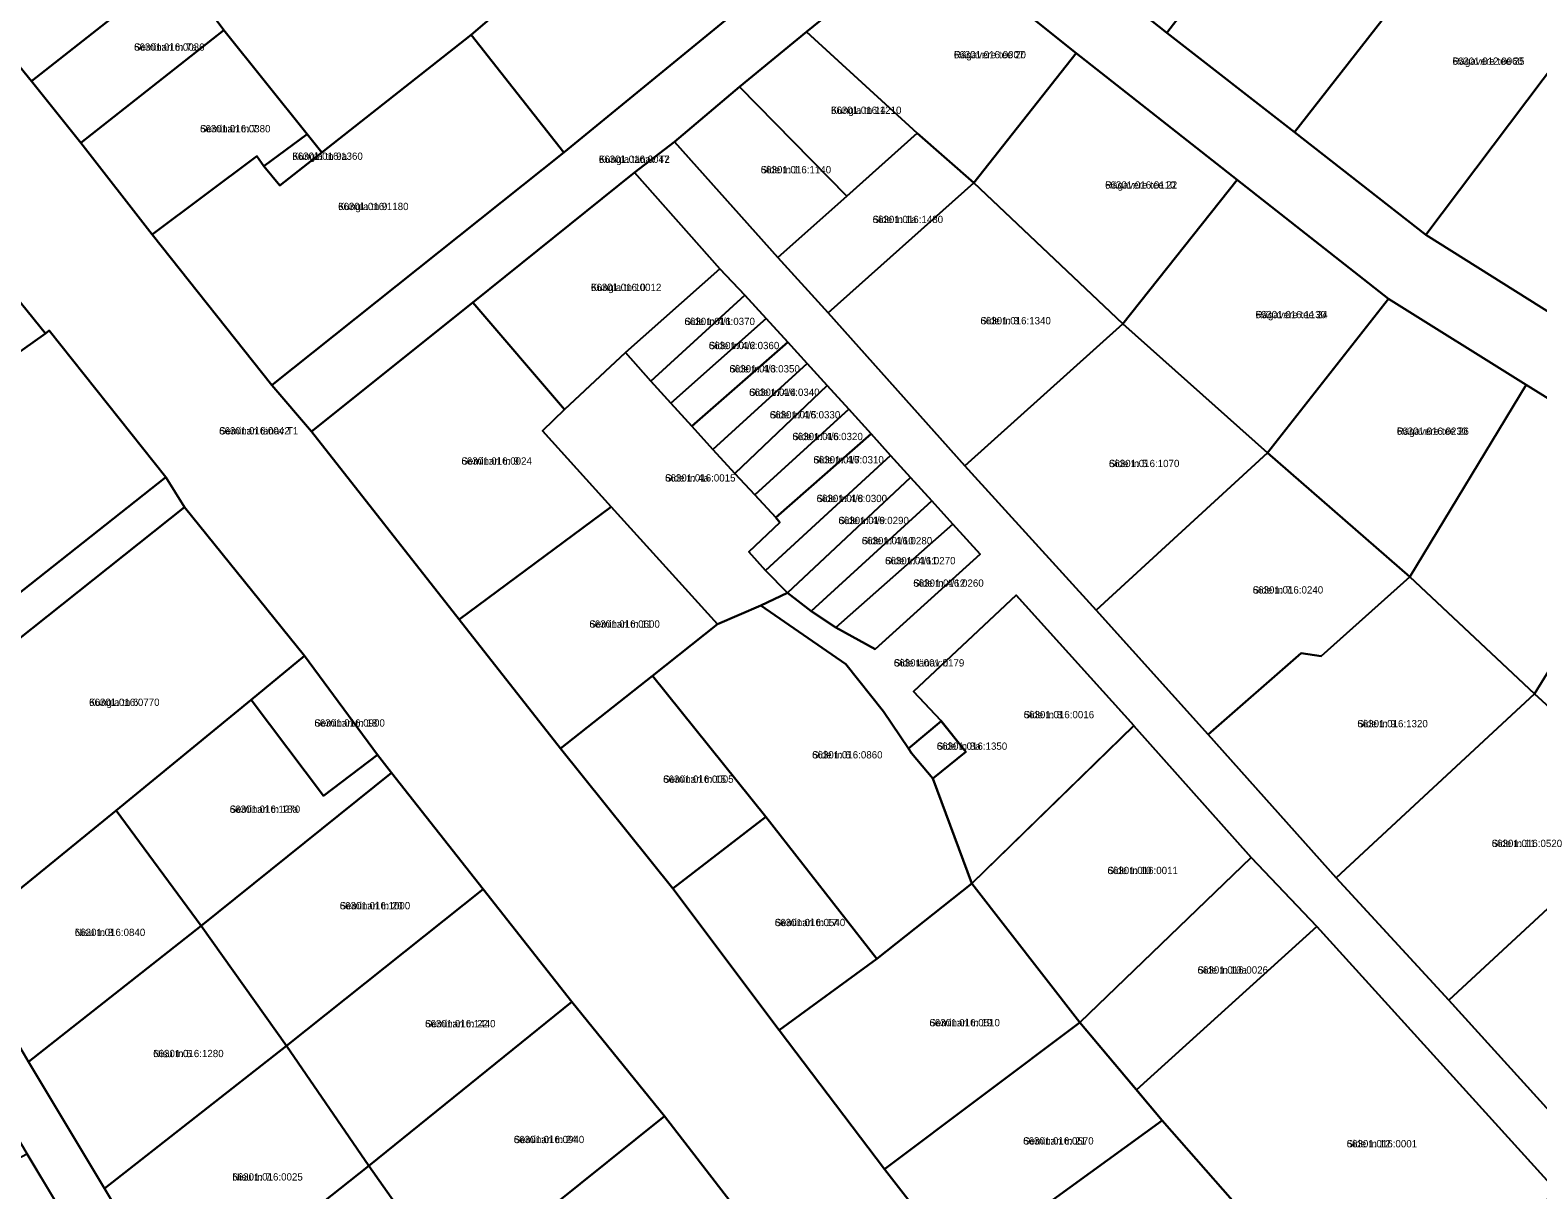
# Model space of a CAD drawing. Extents: x 632278 to 636344, y 6578401 to 6583362.
# Drawn here: x 634783.1 to 635093.3, y 6580529.5 to 6580768.1 of the extents above; entities that cross this region are included whole.
import ezdxf

# ---------------------------------------------------------------- set-up
doc = ezdxf.new("R2010")
doc.units = 0
for name, color, linetype in [('L_AADRESS', 7, 'Continuous'), ('PIIR', 7, 'Continuous'), ('TUNNUS', 7, 'Continuous')]:
    doc.layers.add(name, color=color, linetype=linetype)

msp = doc.modelspace()

# ---------------------------------------------------------------- linework, layer by layer
at = {"layer": 'PIIR'}
for points in [[(634823.24, 6580869.23), (634828.29, 6580865.31), (634831.8, 6580869.51), (634847.15, 6580857.94), (634862.57, 6580846.46), (634870.06, 6580838.92), (634888.87, 6580818.57), (634892.77, 6580814.98), (634907.16, 6580795.65), (634873.8, 6580767.13), (634843.07, 6580742.91), (634840.06, 6580746.68), (634822.92, 6580768.08), (634819.98, 6580772.06), (634822.28, 6580774.15), (634815.33, 6580782.85), (634813.98, 6580781.78), (634811.16, 6580779.56), (634801.59, 6580792.39), (634802.72, 6580793.42), (634817.17, 6580805.59), (634823.5, 6580810.97), (634823.96, 6580814.19), (634803.09, 6580842.19)], [(634873.8, 6580767.13), (634907.16, 6580795.65), (634915.86, 6580804.18), (634929.16, 6580820.76), (634957.76, 6580796.1), (634892.88, 6580742.94)], [(634995.71, 6580821.21), (635034.95, 6580790.95), (635016.95, 6580767.52), (634978.25, 6580798.29)], [(635055.26, 6580817.21), (635075.83, 6580801.21), (635082.16, 6580796.88), (635043.23, 6580747.12), (635016.95, 6580767.52), (635034.95, 6580790.95)], [(634802.72, 6580793.42), (634801.59, 6580792.39), (634811.16, 6580779.56), (634783.36, 6580757.62), (634769.78, 6580774.21), (634799.14, 6580797.48)], [(634832.82, 6580695.01), (634892.88, 6580742.94), (634957.76, 6580796.1), (634967.68, 6580787.95), (634942.84, 6580767.78), (634929.01, 6580756.42), (634915.67, 6580745.14), (634907.44, 6580738.83), (634874.12, 6580712.08), (634840.98, 6580685.48)], [(635043.23, 6580747.12), (635082.16, 6580796.88), (635095.73, 6580785.69), (635108.29, 6580776.43), (635070.3, 6580725.98)], [(634942.84, 6580767.78), (634967.68, 6580787.95), (634998.34, 6580763.36), (634977.26, 6580736.66), (634965.61, 6580746.87)], [(634815.33, 6580782.85), (634822.28, 6580774.15), (634819.98, 6580772.06), (634822.92, 6580768.08), (634793.5, 6580744.88), (634783.36, 6580757.62), (634811.15, 6580779.53), (634813.98, 6580781.78)], [(635070.3, 6580725.98), (635108.29, 6580776.43), (635115.42, 6580770.48), (635135.9, 6580754.85), (635099.43, 6580707.69)], [(634831.13, 6580740.14), (634829.72, 6580742.18), (634808.13, 6580726.06), (634793.5, 6580744.88), (634822.92, 6580768.08), (634840.06, 6580746.68)], [(634808.13, 6580726.06), (634829.72, 6580742.18), (634831.13, 6580740.14), (634834.47, 6580736.14), (634843.07, 6580742.91), (634873.8, 6580767.13), (634892.88, 6580742.94), (634832.82, 6580695.01)], [(634942.84, 6580767.78), (634965.61, 6580746.87), (634951.12, 6580733.96), (634929.01, 6580756.42)], [(635031.47, 6580737.28), (635007.9, 6580707.63), (634977.26, 6580736.66), (634998.34, 6580763.36)], [(634936.92, 6580721.34), (634915.67, 6580745.14), (634929.01, 6580756.42), (634951.12, 6580733.96)], [(634831.13, 6580740.14), (634840.06, 6580746.68), (634843.07, 6580742.91), (634834.47, 6580736.14)], [(634936.92, 6580721.34), (634951.12, 6580733.96), (634965.61, 6580746.87), (634977.26, 6580736.66), (634947.28, 6580709.92)], [(634907.44, 6580738.83), (634925, 6580718.99), (634905.59, 6580701.73), (634893, 6580690.02), (634874.12, 6580712.08)], [(634947.28, 6580709.92), (634977.26, 6580736.66), (635007.9, 6580707.63), (634975.39, 6580678.46)], [(635031.47, 6580737.28), (635062.56, 6580712.81), (635037.69, 6580681.14), (635007.9, 6580707.63)], [(634754.64, 6580720.33), (634767.52, 6580728.66), (634786.21, 6580705.69), (634769.31, 6580693.77), (634750.53, 6580717.31)], [(634905.59, 6580701.73), (634925, 6580718.99), (634930.14, 6580713.55), (634910.79, 6580695.84)], [(634874.12, 6580712.08), (634893, 6580690.02), (634888.51, 6580685.67), (634902.65, 6580669.99), (634871.35, 6580646.8), (634840.98, 6580685.48)], [(634910.79, 6580695.84), (634930.14, 6580713.55), (634934.55, 6580708.75), (634914.89, 6580691.34)], [(635090.91, 6580695.09), (635066.99, 6580655.6), (635037.69, 6580681.14), (635062.56, 6580712.81)], [(634914.89, 6580691.34), (634934.55, 6580708.75), (634939, 6580703.9), (634919.22, 6580686.57)], [(634975.39, 6580678.46), (635007.9, 6580707.63), (635037.69, 6580681.14), (635002.44, 6580648.74)], [(634723.93, 6580659.68), (634730.28, 6580664.53), (634721.26, 6580676.15), (634722.32, 6580678.87), (634732.5, 6580687.67), (634740.73, 6580676.25), (634749.82, 6580683.43), (634750.6, 6580682.22), (634752.63, 6580681.59), (634769.31, 6580693.77), (634786.21, 6580705.69), (634786.98, 6580706.28), (634810.95, 6580676.09), (634749.17, 6580627.28)], [(634905.59, 6580701.73), (634910.79, 6580695.84), (634914.89, 6580691.34), (634919.22, 6580686.57), (634923.56, 6580681.78), (634928.1, 6580676.87), (634932.18, 6580672.48), (634936.51, 6580667.78), (634937.35, 6580666.77), (634930.97, 6580660.76), (634934.41, 6580656.91), (634938.91, 6580652.32), (634933.4, 6580649.71), (634924.52, 6580645.84), (634902.65, 6580669.99), (634888.51, 6580685.67), (634893, 6580690.02)], [(634923.56, 6580681.78), (634919.22, 6580686.57), (634939, 6580703.9), (634942.97, 6580699.52)], [(634923.56, 6580681.78), (634942.97, 6580699.52), (634947.05, 6580694.97), (634928.1, 6580676.87)], [(634932.18, 6580672.48), (634928.1, 6580676.87), (634947.05, 6580694.97), (634951.54, 6580690.09)], [(635066.99, 6580655.6), (635090.91, 6580695.09), (635120.58, 6580676.71), (635092.61, 6580631.5)], [(634932.18, 6580672.48), (634951.54, 6580690.09), (634956.11, 6580685.04), (634936.51, 6580667.78)], [(634930.97, 6580660.76), (634937.35, 6580666.77), (634936.51, 6580667.78), (634956.11, 6580685.04), (634960.09, 6580680.58), (634934.41, 6580656.91)], [(634934.41, 6580656.91), (634960.09, 6580680.58), (634964.24, 6580676.02), (634938.91, 6580652.32)], [(635002.44, 6580648.74), (635037.69, 6580681.14), (635066.99, 6580655.6), (635048.71, 6580639.29), (635044.62, 6580639.92), (635025.47, 6580623.18)], [(635118.04, 6580608.34), (635092.61, 6580631.5), (635120.58, 6580676.71), (635149.13, 6580659)], [(634627.56, 6580552.33), (634672.16, 6580573.77), (634697.15, 6580585.77), (634749.17, 6580627.28), (634810.95, 6580676.09), (634814.85, 6580669.93), (634751.98, 6580619.99), (634754.12, 6580617.28), (634691.25, 6580567.83), (634680.94, 6580563.02), (634659.14, 6580553.09), (634633.69, 6580540.22)], [(634938.91, 6580652.32), (634964.24, 6580676.02), (634968.59, 6580671.22), (634943.8, 6580648.55)], [(634943.8, 6580648.55), (634968.59, 6580671.22), (634972.96, 6580666.42), (634948.89, 6580645.15)], [(634754.12, 6580617.28), (634751.98, 6580619.99), (634814.85, 6580669.93), (634839.5, 6580639.31), (634828.53, 6580630.32), (634800.72, 6580607.55), (634777.05, 6580588.16)], [(634911.12, 6580635.26), (634892.17, 6580620.29), (634871.35, 6580646.8), (634902.65, 6580669.99), (634924.52, 6580645.84)], [(634978.57, 6580660.25), (634956.93, 6580640.7), (634948.89, 6580645.15), (634972.96, 6580666.42)], [(635025.47, 6580623.18), (635044.62, 6580639.92), (635048.71, 6580639.29), (635066.99, 6580655.6), (635092.61, 6580631.5), (635051.82, 6580593.68)], [(634985.94, 6580651.81), (635010.2, 6580625.04), (634976.83, 6580592.52), (634968.81, 6580614.09), (634975.63, 6580619.58), (634970.46, 6580626.03), (634964.82, 6580632.01)], [(634911.12, 6580635.26), (634924.52, 6580645.84), (634933.4, 6580649.71), (634950.9, 6580637.66), (634958.68, 6580627.87), (634963.8, 6580620.27), (634964.45, 6580619.32), (634968.81, 6580614.09), (634976.83, 6580592.52), (634957.27, 6580576.99), (634934.47, 6580606.2)], [(634839.5, 6580639.31), (634854.56, 6580618.94), (634843.41, 6580610.54), (634828.53, 6580630.32)], [(634892.17, 6580620.29), (634911.12, 6580635.26), (634934.47, 6580606.2), (634915.3, 6580591.45)], [(634800.72, 6580607.55), (634828.53, 6580630.32), (634843.41, 6580610.54), (634854.56, 6580618.94), (634857.4, 6580615.3), (634818.26, 6580583.76)], [(635051.82, 6580593.68), (635092.61, 6580631.5), (635118.04, 6580608.34), (635099.96, 6580591.6), (635075.02, 6580568.5)], [(634964.45, 6580619.32), (634963.8, 6580620.27), (634970.54, 6580625.93), (634975.63, 6580619.58), (634968.81, 6580614.09)], [(634976.83, 6580592.52), (635010.19, 6580624.94), (635034.3, 6580597.86), (634999.05, 6580563.91)], [(634857.4, 6580615.3), (634876.28, 6580591.36), (634835.81, 6580559.06), (634818.26, 6580583.76)], [(634767.93, 6580580.95), (634777.05, 6580588.16), (634800.72, 6580607.55), (634818.26, 6580583.76), (634782.69, 6580555.83)], [(634915.3, 6580591.45), (634934.47, 6580606.2), (634957.27, 6580576.99), (634937.2, 6580562.34)], [(635034.3, 6580597.86), (635047.82, 6580583.64), (635010.71, 6580550.04), (634999.05, 6580563.91)], [(634835.81, 6580559.06), (634876.28, 6580591.36), (634894.54, 6580568.16), (634852.77, 6580534.43)], [(634958.84, 6580533.7), (634937.2, 6580562.34), (634957.27, 6580576.99), (634976.83, 6580592.52), (634999.05, 6580563.91)], [(635099.96, 6580591.6), (635132.14, 6580557.24), (635105.18, 6580535.22), (635075.02, 6580568.5)], [(634782.69, 6580555.83), (634818.26, 6580583.76), (634835.81, 6580559.06), (634798.34, 6580529.75)], [(635047.82, 6580583.64), (635097.24, 6580529.16), (635056.99, 6580495.94), (635037.46, 6580519.29), (635016.03, 6580543.71), (635010.71, 6580550.04)], [(634759.96, 6580574.64), (634767.92, 6580580.95), (634782.68, 6580555.83), (634798.34, 6580529.75), (634813.99, 6580503.67), (634829.51, 6580477.96), (634844.88, 6580452.32), (634863.82, 6580429.05), (634882.83, 6580405.8), (634908.99, 6580374.54), (634900.81, 6580367.9), (634892.91, 6580377.7), (634875.42, 6580398.72), (634857.07, 6580420.87), (634837.67, 6580444.04), (634824.12, 6580466.81), (634809.96, 6580490.2), (634796.37, 6580513.12), (634794.4, 6580516.88), (634782.42, 6580536.86)], [(634852.77, 6580534.43), (634894.54, 6580568.16), (634913.57, 6580544.61), (634890.36, 6580525.99), (634869.97, 6580509.97)], [(634958.84, 6580533.7), (634999.05, 6580563.91), (635016.03, 6580543.71), (634974.53, 6580513.64)], [(634798.34, 6580529.75), (634835.81, 6580559.06), (634852.77, 6580534.43), (634814, 6580503.67)], [(634893.66, 6580523.69), (634892.93, 6580523.09), (634890.36, 6580525.99), (634913.57, 6580544.61), (634928.91, 6580524.79), (634906.87, 6580507.48)], [(634974.53, 6580513.64), (635016.03, 6580543.71), (635037.46, 6580519.29), (634997.58, 6580485.98)], [(634759.43, 6580524.63), (634782.38, 6580536.89), (634794.4, 6580516.88), (634771.66, 6580504.17)], [(634869.97, 6580509.97), (634829.51, 6580477.96), (634814, 6580503.67), (634852.77, 6580534.43)]]:
    msp.add_lwpolyline(points, close=True, dxfattribs=at)
for points in [[(634978.25, 6580798.29), (635016.95, 6580767.52), (635043.23, 6580747.12), (635070.3, 6580725.98), (635099.43, 6580707.69), (635128.62, 6580689.79), (635157.41, 6580671.94), (635205.38, 6580642.24), (635196.45, 6580630.3), (635177.25, 6580641.51), (635149.13, 6580659), (635120.58, 6580676.71), (635090.91, 6580695.09), (635062.56, 6580712.81), (635031.47, 6580737.28), (634998.34, 6580763.36), (634967.68, 6580787.95)], [(634769.78, 6580774.21), (634783.36, 6580757.62), (634793.5, 6580744.88), (634808.13, 6580726.06), (634832.82, 6580695.01), (634840.98, 6580685.48), (634871.35, 6580646.8), (634892.17, 6580620.29), (634915.3, 6580591.45), (634937.2, 6580562.34), (634958.84, 6580533.7), (634974.53, 6580513.64)], [(635097.24, 6580529.16), (635047.82, 6580583.64), (635034.3, 6580597.86), (635010.19, 6580624.94), (635010.2, 6580625.04), (634985.94, 6580651.81), (634964.82, 6580632.01), (634970.46, 6580626.03), (634970.54, 6580625.93), (634963.8, 6580620.27), (634958.68, 6580627.87), (634950.9, 6580637.66), (634933.4, 6580649.71), (634938.91, 6580652.32), (634943.8, 6580648.55), (634948.89, 6580645.15), (634956.93, 6580640.7), (634978.57, 6580660.25), (634972.96, 6580666.42), (634968.59, 6580671.22), (634964.24, 6580676.02), (634960.09, 6580680.58), (634956.11, 6580685.04), (634951.54, 6580690.09), (634947.05, 6580694.97), (634942.97, 6580699.52), (634939, 6580703.9), (634934.55, 6580708.75), (634930.14, 6580713.55), (634925, 6580718.99), (634907.44, 6580738.83), (634915.67, 6580745.14), (634936.92, 6580721.34), (634947.28, 6580709.92), (634975.39, 6580678.46), (635002.44, 6580648.74), (635025.47, 6580623.18), (635051.82, 6580593.68), (635075.02, 6580568.5), (635105.18, 6580535.22)], [(634928.91, 6580524.79), (634913.57, 6580544.61), (634894.54, 6580568.16), (634876.28, 6580591.36), (634857.4, 6580615.3), (634854.56, 6580618.94), (634839.5, 6580639.31), (634814.85, 6580669.93), (634810.95, 6580676.09), (634786.98, 6580706.28), (634786.21, 6580705.69), (634767.52, 6580728.66)]]:
    msp.add_lwpolyline(points, dxfattribs=at)

# ---------------------------------------------------------------- texts
at = {"layer": 'L_AADRESS'}
for s, p in [('Seminari tn 7a', (634804.43, 6580763.87)), ('Rägavere tee 20', (634973.15, 6580762.3)), ('Rägavere tee 25', (635075.76, 6580760.97)), ('Kungla tn 14', (634947.86, 6580750.87)), ('Seminari tn 7', (634818.01, 6580747.07)), ('Kungla tn 9a', (634837.01, 6580741.41)), ('Kungla tänav T2', (634900.09, 6580740.79)), ('Side tn 1', (634933.39, 6580738.63)), ('Rägavere tee 22', (635004.27, 6580735.49)), ('Kungla tn 9', (634846.42, 6580731.07)), ('Side tn 1a', (634956.43, 6580728.4)), ('Kungla tn 10', (634898.45, 6580714.42)), ('Side tn 4/1', (634917.71, 6580707.41)), ('Side tn 3', (634978.61, 6580707.56)), ('Rägavere tee 24', (635035.23, 6580708.82)), ('Side tn 4/2', (634922.72, 6580702.45)), ('Side tn 4/3', (634926.95, 6580697.66)), ('Side tn 4/4', (634931.02, 6580692.84)), ('Side tn 4/5', (634935.27, 6580688.2)), ('Seminari tänav T1', (634821.95, 6580684.9)), ('Rägavere tee 26', (635064.3, 6580684.83)), ('Side tn 4/6', (634939.91, 6580683.73)), ('Seminari tn 9', (634871.81, 6580678.69)), ('Side tn 4/7', (634944.23, 6580678.94)), ('Side tn 5', (635005.06, 6580678.18)), ('Side tn 4a', (634913.71, 6580675.21)), ('Side tn 4/8', (634944.9, 6580670.98)), ('Side tn 4/9', (634949.39, 6580666.45)), ('Side tn 4/10', (634954.19, 6580662.29)), ('Side tn 4/11', (634958.99, 6580658.18)), ('Side tn 4/12', (634964.79, 6580653.56)), ('Side tn 7', (635034.65, 6580652.16)), ('Seminari tn 11', (634898.14, 6580645.14)), ('Side tänav L1', (634960.8, 6580637.15)), ('Kungla tn 6', (634795.18, 6580629.04)), ('Side tn 8', (634987.51, 6580626.5)), ('Seminari tn 18', (634841.55, 6580624.78)), ('Side tn 9', (635056.18, 6580624.64)), ('Side tn 8a', (634969.63, 6580620.01)), ('Side tn 6', (634943.97, 6580618.23)), ('Seminari tn 15', (634913.32, 6580613.22)), ('Seminari tn 18a', (634824.12, 6580607.04)), ('Side tn 11', (635083.83, 6580600)), ('Side tn 10', (635004.76, 6580594.43)), ('Seminari tn 20', (634846.77, 6580587.18)), ('Seminari tn 17', (634936.29, 6580583.72)), ('Nisu tn 3', (634792.24, 6580581.69)), ('Side tn 10a', (635023.3, 6580573.95)), ('Seminari tn 22', (634864.32, 6580562.9)), ('Seminari tn 19', (634968.12, 6580563.11)), ('Nisu tn 5', (634808.37, 6580556.76)), ('Seminari tn 24', (634882.58, 6580539.07)), ('Seminari tn 21', (634987.41, 6580538.78)), ('Side tn 12', (635053.98, 6580538.2)), ('Nisu tn 7', (634824.66, 6580531.37))]:
    msp.add_text(s, height=1.5, dxfattribs=at).set_placement(p)
at = {"layer": 'TUNNUS'}
for s, p in [('66301:016:0036', (634804.43, 6580763.87)), ('66301:016:0007', (634973.15, 6580762.3)), ('66301:012:0060', (635075.76, 6580760.97)), ('66301:016:1210', (634947.86, 6580750.87)), ('66301:016:0380', (634818.01, 6580747.07)), ('66301:016:1360', (634837.01, 6580741.41)), ('66301:016:0047', (634900.09, 6580740.79)), ('66301:016:1140', (634933.39, 6580738.63)), ('66301:016:0110', (635004.27, 6580735.49)), ('66301:016:1180', (634846.42, 6580731.07)), ('66301:016:1480', (634956.43, 6580728.4)), ('66301:016:0012', (634898.45, 6580714.42)), ('66301:016:0370', (634917.71, 6580707.41)), ('66301:016:1340', (634978.61, 6580707.56)), ('66301:016:1130', (635035.23, 6580708.82)), ('66301:016:0360', (634922.72, 6580702.45)), ('66301:016:0350', (634926.95, 6580697.66)), ('66301:016:0340', (634931.02, 6580692.84)), ('66301:016:0330', (634935.27, 6580688.2)), ('66301:016:0042', (634821.95, 6580684.9)), ('66301:016:0230', (635064.3, 6580684.83)), ('66301:016:0320', (634939.91, 6580683.73)), ('66301:016:0024', (634871.81, 6580678.69)), ('66301:016:0310', (634944.23, 6580678.94)), ('66301:016:1070', (635005.06, 6580678.18)), ('66301:016:0015', (634913.71, 6580675.21)), ('66301:016:0300', (634944.9, 6580670.98)), ('66301:016:0290', (634949.39, 6580666.45)), ('66301:016:0280', (634954.19, 6580662.29)), ('66301:016:0270', (634958.99, 6580658.18)), ('66301:016:0260', (634964.79, 6580653.56)), ('66301:016:0240', (635034.65, 6580652.16)), ('66301:016:0600', (634898.14, 6580645.14)), ('66301:001:0179', (634960.8, 6580637.15)), ('66301:016:0770', (634795.18, 6580629.04)), ('66301:016:0016', (634987.51, 6580626.5)), ('66301:016:0900', (634841.55, 6580624.78)), ('66301:016:1320', (635056.18, 6580624.64)), ('66301:016:1350', (634969.63, 6580620.01)), ('66301:016:0860', (634943.97, 6580618.23)), ('66301:016:0005', (634913.32, 6580613.22)), ('66301:016:1270', (634824.12, 6580607.04)), ('66301:016:0520', (635083.83, 6580600)), ('66301:016:0011', (635004.76, 6580594.43)), ('66301:016:1000', (634846.77, 6580587.18)), ('66301:016:0540', (634936.29, 6580583.72)), ('66301:016:0840', (634792.24, 6580581.69)), ('66301:016:0026', (635023.3, 6580573.95)), ('66301:016:1440', (634864.32, 6580562.9)), ('66301:016:0510', (634968.12, 6580563.11)), ('66301:016:1280', (634808.37, 6580556.76)), ('66301:016:0940', (634882.58, 6580539.07)), ('66301:016:0570', (634987.41, 6580538.78)), ('66301:016:0001', (635053.98, 6580538.2)), ('66301:016:0025', (634824.66, 6580531.37))]:
    msp.add_text(s, height=1.5, dxfattribs=at).set_placement(p)

doc.saveas('drawing.dxf')
